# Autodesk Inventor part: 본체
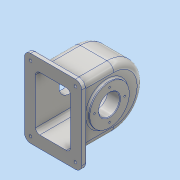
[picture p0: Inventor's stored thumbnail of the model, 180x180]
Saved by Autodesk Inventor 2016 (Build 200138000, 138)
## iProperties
Created: 2018-11
Part Number: 본체
Material: 알루미늄 6061
Document SubType Name: Modeling
Designer: user
Density: 2.7 g/cm^3
Appearance: 알루미늄 - 평지
Mass: 1091.9 g
Surface Area: 1182.65 cm^2
Volume: 404.407 cm^3
Author: user
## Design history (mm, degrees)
sketch "스케치1"
  geometry: L1 (-55, 75)-(55, 75); L2 (55, 75)-(55, -75); L3 (55, -75)-(-55, -75); L4 (-55, -75)-(-55, 75); L5 (-55, 75)-(55, -75); L6 (55, 75)-(-55, -75); 1 further point
  constraints: 12 end point, 2 midpoint, 2 parallel, 1 horizontal, 1 perpendicular
  dimensions: "d0" = 150 distance of L1.end L2.end; "d1" = 110 distance of L1.start L1.end
extrude "돌출1" new body sketch "스케치1" distance "d2" = 10; taper "d3" = 0 deg
node "작업 평면1"
sketch "스케치5"
  geometry: L1 (78, 58)-(10, 58); L2 (10, -75)-(10, 75) reference; L3 (78, -58)-(10, -58); A1 r 58 centre (78, 0) between (78, -58) and (78, 58); 1 further point
  constraints: 4 end point, 2 point on circle, 2 point on line, 2 tangent, 1 centre point, 1 horizontal, 1 horizontal alignment, 1 perpendicular
  dimensions: "d5" = 78 distance of point (0, 0) A1.centre; "d6" = 116 diameter of A1
extrude "돌출2" join sketch "스케치5" stored distance "d7" = 77; taper "d8" = 0 deg
sketch "스케치6"
  geometry: L1 (75, 0)-(-75, 0) reference; C1 r 38 at (0, 65); 2 further points
  constraints: 1 centre point, 1 midpoint, 1 vertical alignment
  dimensions: "d11" = 76 diameter of C1; "d12" = 65 distance from line of L1 C1.centre
extrude "돌출3" join sketch "스케치6" distance "d13" = 5; taper "d14" = 0 deg
sketch "스케치7"
  geometry: L1 (75, 0)-(-75, 0) reference; C1 r 38 at (0, 65); 2 further points
  constraints: 1 centre point, 1 midpoint, 1 vertical alignment
  dimensions: "d15" = 76 diameter of C1; "d16" = 65 distance from line of L1 C1.centre
extrude "돌출4" join sketch "스케치7" distance "d17" = 10; taper "d18" = 0 deg
sketch "스케치11"
  geometry: L1 (10, -58)-(78, -58) reference; L2 (78, 58)-(10, 58) reference; L3 (0, 52)-(78, 52); L4 (78, -52)-(0, -52); L5 (0, -75)-(0, 75) reference; L6 (0, -52)-(0, 52); A1 r 58 centre (78, 0) between (78, -58) and (78, 58) reference; A2 r 52 centre (78, 0) between (78, -52) and (78, 52); 1 further point
  constraints: 6 end point, 2 horizontal, 2 point on circle, 2 point on line, 2 tangent, 1 centre point, 1 collinear
  dimensions: "d31" = 6 radial gap between concentric circles of A1 A2
extrude "돌출6" cut sketch "스케치11" stored distance "d32" = 67; taper "d33" = 0 deg
sketch "스케치12"
  geometry: C1 r 20 at (0, 0); C2 r 38 at (0, 0) reference; 1 further point
  constraints: 1 centre point, 1 concentric
  dimensions: "d34" = 40 diameter of C1
extrude "돌출7" cut sketch "스케치12" distance "d35" = 24; taper "d36" = 0 deg
sketch "스케치13"
  geometry: C1 r 20 at (0, 0); C2 r 38 at (0, 0) reference; 1 further point
  constraints: 1 centre point, 1 concentric
  dimensions: "d37" = 40 diameter of C1
extrude "돌출8" cut sketch "스케치13" distance "d38" = 15; taper "d39" = 0 deg
node "작업 평면3"
sketch "스케치16"
  geometry: C1 r 6 at (0, 0); 1 further point
  constraints: 1 centre point, 1 coincident
  dimensions: "d42" = 12 diameter of C1
extrude "돌출9" join sketch "스케치16" stored distance "d43" = 15; taper "d44" = 5 deg
node "작업 평면4"
sketch "스케치18"
  geometry: C1 r 6 at (0, 0) reference; 1 further point
hole "구멍1" sketch "스케치18" at (0, 0) diameter "d47" = 4.459; stored, may be unused: countersink angle "d51" = 90 deg, drill point angle "d53" = 118 deg; dims "d48" = 10, "d49" = 4, "d50" = 2, "d52" = 30
sketch "스케치19" dims "d54" = 58
  geometry: C1 r 38 at (0, 0) reference; 3 further points
  constraints: 2 vertical alignment, 3 other
hole "구멍2" sketch "스케치19" at (0, 29) diameter "d55" = 3.242; stored, may be unused: countersink angle "d59" = 90 deg, drill point angle "d61" = 118 deg; dims "d56" = 8, "d57" = 4, "d58" = 2, "d60" = 10
fillet "모깎기1" dims "d76" = 12
sketch "스케치21"
  geometry: A1 r 12 centre (43, -63) between (43, -75) and (55, -63) reference; A2 r 12 centre (-43, -63) between (-55, -63) and (-43, -75) reference; A3 r 12 centre (-43, 63) between (-43, 75) and (-55, 63) reference; A4 r 12 centre (43, 63) between (55, 63) and (43, 75) reference; 1 further point
hole "구멍4" sketch "스케치21" at (43, 63), (-43, 63), (43, -63), (-43, -63) diameter "d77" = 5; stored, may be unused: countersink angle "d81" = 90 deg, drill point angle "d83" = 118 deg; dims "d78" = 8, "d79" = 12, "d80" = 4, "d82" = 10
fillet "모깎기2" dims "d84" = 3
fillet "모깎기3" dims "d85" = 13
sketch "스케치23"
  geometry: C1 r 28 at (0, 65); C2 r 20 at (0, 65) reference; 1 further point
  constraints: 1 centre point, 1 concentric
  dimensions: "d86" = 56 diameter of C1
extrude "돌출10" join sketch "스케치23" distance "d87" = 14; taper "d88" = 0 deg
feature "면 기울기2" dims angle "d89" = 40 deg
sketch "스케치24" dims "d90" = 58
  geometry: C1 r 39.747 at (0, 0) reference; 3 further points
  constraints: 2 vertical alignment, 1 coincident, 2 other
hole "구멍5" sketch "스케치24" at (0, 29) diameter "d91" = 3.242; stored, may be unused: countersink angle "d95" = 90 deg, drill point angle "d97" = 118 deg; dims "d92" = 8, "d93" = 12, "d94" = 4, "d96" = 10
fillet "모깎기4" dims "d101" = 3
fillet "모깎기5" dims "d102" = 3
fillet "모깎기6" dims "d103" = 8
fillet "모깎기7" dims "d104" = 3
chamfer "모따기1" distance "d105" = 1; stored, may be unused: second distance "d106" = 2, angle "d107" = 45 deg
chamfer "모따기2" distance "d108" = 1; stored, may be unused: second distance "d109" = 2, angle "d110" = 45 deg
sketch "스케치25"
  geometry: L1 (-13, 0)-(-13, -65) reference; L2 (68.5, -78)-(-17.5, -78) reference; 2 further points
  constraints: 1 other
  dimensions: "d111" = 38.5 distance from line of L1 point (25.5, -38); "d112" = 40 distance from line of L2 point (25.5, -38)
feature "엠보싱1" sketch "스케치25" dims "d113" = 0.5, "d114" = 0
node "솔리드1"
pattern_circular "원형 패턴1" dims angle "d63" = 360 deg
pattern_circular "원형 패턴3" dims angle "d99" = 360 deg
other parameters: "d4" = 0, "d41" = -142, "d45" = 126.75
